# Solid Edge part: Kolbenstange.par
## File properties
Username: bmolnar
Dokumentum tartalom típus: 0
Author: bmolnar
Last saved by: bmolnar
Revision: 82
Sűrűség: 0,000 kg/m^3
Pontosság: 0,990
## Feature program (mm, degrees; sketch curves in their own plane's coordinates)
base feature "unnamed BaseFeature 1"
sketch for "unnamed Protrusion 1" plane through (0, 0, -26) normal (0, 0, -1) x-axis (1, 0, 0)
  circle centre (0, 0) radius 25
extrude "unnamed Protrusion 1" add finite 13.5 along +normal
sketch for "Kihúzás_2" plane through (0, 0, -26) normal (0, 0, -1) x-axis (1, 0, 0)
  circle centre (0, 0) radius 25
extrude "Kihúzás_2" add finite 2.5 along -normal
thread "unnamed Thread 1"
chamfer "Letörés_1" setback 2.75  SetBackValue2 = 20 deg
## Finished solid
Body 1: solid body, 17 faces, 23 edges, 8 vertices.
  Faces by surface: plane 8, cylinder 4, torus 3, cone 2
  Edges by curve: circle 13, line 6, ellipse 2, intersection 2
Bounding box of the edges (mm; curved faces can reach further): 50.000 x 50.000 x 85.500, from (-25, -25, -39.5) to (25, 25, 46).
Cylindrical faces by radius (mm): R5 x1, R6 x1, R8 x1, R25 x1
Conical faces (half-angle, radius in mm at the cone's reference point): 20 deg R4.9991 x1, 60 deg R5.6 x1
Toroidal faces (ring radius, tube radius in mm): R5.4 r0.4 x2, R6.3 r1.7 x1
Planar faces by outward normal: +x 1, +z 3, -x 1, -z 1, oblique 2
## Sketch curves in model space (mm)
circle centre (0, 0, -26) radius 25
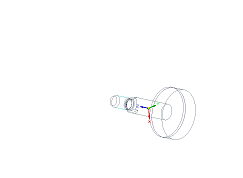
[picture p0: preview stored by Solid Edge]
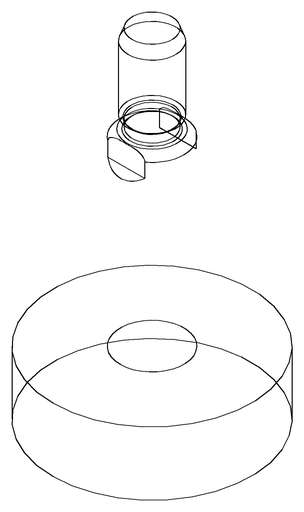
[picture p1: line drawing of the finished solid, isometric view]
